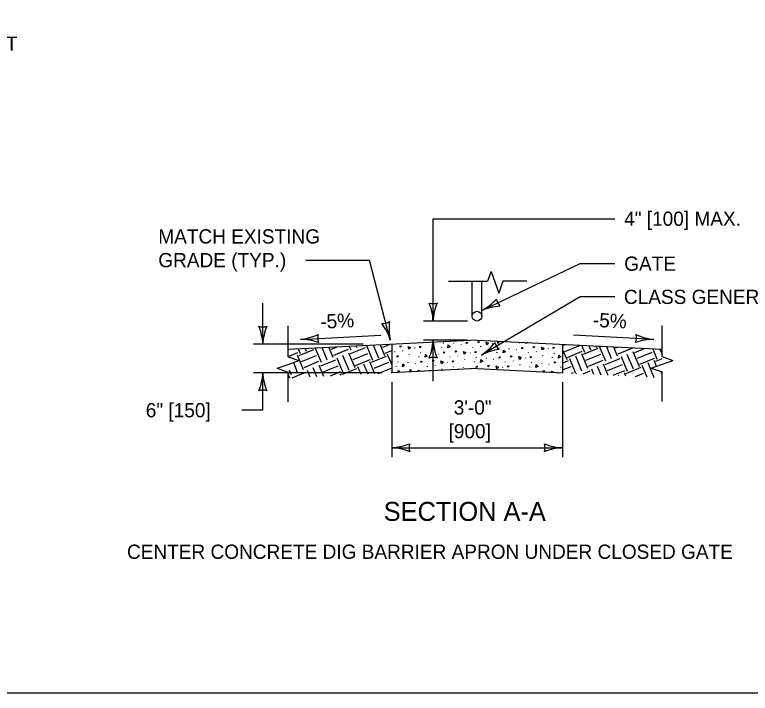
# Model space of a CAD drawing. Extents: x 49991.4 to 50021, y 49987.6 to 50011.4.
# Drawn here: x 50010.385 to 50013.487, y 49987.799 to 49990.66 of the extents above; entities that cross this region are included whole.
import ezdxf

# ---------------------------------------------------------------- set-up
doc = ezdxf.new("R2010")
doc.units = 0
for name, color, linetype in [('Level 1', 7, 'Continuous'), ('Level 2', 7, 'Continuous'), ('Level 3', 7, 'Continuous'), ('Level 6', 7, 'Continuous')]:
    doc.layers.add(name, color=color, linetype=linetype)

msp = doc.modelspace()

# ---------------------------------------------------------------- linework, layer by layer
at = {"layer": 'Level 1'}
for p, q in [((50012.3141, 49989.3891), (50012.3141, 49989.537)), ((50012.3552, 49989.3891), (50012.3552, 49989.537)), ((50012.3347, 49989.2886), (50011.5381, 49989.2488)), ((50012.3347, 49989.2886), (50013.1145, 49989.2496)), ((50011.6096, 49989.2524), (50011.6139, 49989.242)), ((50011.6096, 49989.2524), (50011.6139, 49989.242)), ((50011.6383, 49989.2538), (50011.6389, 49989.2524)), ((50011.6383, 49989.2538), (50011.6389, 49989.2524)), ((50011.6522, 49989.2545), (50011.6767, 49989.1952)), ((50011.6522, 49989.2545), (50011.6767, 49989.1952)), ((50011.6809, 49989.2559), (50011.7018, 49989.2056)), ((50011.6809, 49989.2559), (50011.7018, 49989.2056)), ((50011.7097, 49989.2574), (50011.7268, 49989.2159)), ((50011.7097, 49989.2574), (50011.7268, 49989.2159)), ((50011.7201, 49989.2498), (50011.7423, 49989.259)), ((50011.7201, 49989.2498), (50011.7423, 49989.259)), ((50011.7959, 49989.2617), (50011.802, 49989.2471)), ((50011.7959, 49989.2617), (50011.802, 49989.2471)), ((50011.8012, 49989.2312), (50011.8638, 49989.2572)), ((50011.8012, 49989.2312), (50011.8638, 49989.2572)), ((50011.8247, 49989.2631), (50011.827, 49989.2574)), ((50011.8247, 49989.2631), (50011.827, 49989.2574)), ((50011.8683, 49989.2653), (50011.8941, 49989.2032)), ((50011.8683, 49989.2653), (50011.8941, 49989.2032)), ((50011.8971, 49989.2667), (50011.9191, 49989.2135)), ((50011.8971, 49989.2667), (50011.9191, 49989.2135)), ((50011.9258, 49989.2682), (50011.9442, 49989.2239)), ((50011.9258, 49989.2682), (50011.9442, 49989.2239)), ((50011.9368, 49989.2581), (50011.966, 49989.2702)), ((50011.9368, 49989.2581), (50011.966, 49989.2702)), ((50011.9746, 49989.2706), (50011.9746, 49989.1505)), ((50012.0715, 49989.2564), (50012.0724, 49989.2547)), ((50012.1455, 49989.2658), (50012.1455, 49989.2679)), ((50012.1859, 49989.2565), (50012.186, 49989.2586)), ((50012.1916, 49989.2762), (50012.1929, 49989.2753)), ((50012.1926, 49989.2761), (50012.1938, 49989.2752)), ((50012.2362, 49989.272), (50012.2363, 49989.2741)), ((50012.2665, 49989.2695), (50012.2678, 49989.2686)), ((50012.3173, 49989.2556), (50012.3174, 49989.2577)), ((50012.3511, 49989.26), (50012.3512, 49989.2621)), ((50012.4008, 49989.2747), (50012.4017, 49989.273)), ((50012.425, 49989.2548), (50012.4263, 49989.2539)), ((50012.426, 49989.2546), (50012.4273, 49989.2538)), ((50012.4697, 49989.2505), (50012.4697, 49989.2526)), ((50012.5152, 49989.2747), (50012.5152, 49989.2769)), ((50012.6342, 49989.2532), (50012.6351, 49989.2515)), ((50012.6947, 49989.2706), (50012.6947, 49989.1505)), ((50012.6947, 49989.265), (50012.7068, 49989.27)), ((50012.7051, 49989.24), (50012.7677, 49989.2659)), ((50012.7753, 49989.2666), (50012.7876, 49989.2369)), ((50012.7833, 49989.2283), (50012.8459, 49989.2543)), ((50012.8053, 49989.2651), (50012.8127, 49989.2473)), ((50012.8353, 49989.2636), (50012.8377, 49989.2577)), ((50012.8497, 49989.2629), (50012.8755, 49989.2005)), ((50012.8797, 49989.2614), (50012.9006, 49989.2109)), ((50012.9096, 49989.2599), (50012.9256, 49989.2213)), ((50012.9189, 49989.2552), (50012.9281, 49989.259)), ((50012.9293, 49989.2301), (50012.9913, 49989.2558)), ((50012.9995, 49989.2554), (50013.0008, 49989.2524)), ((50013, 49989.2366), (50013.0405, 49989.2533)), ((50011.5381, 49989.2478), (50011.5408, 49989.2489)), ((50011.5381, 49989.2184), (50011.5793, 49989.2355)), ((50011.5756, 49989.2267), (50011.6016, 49989.164)), ((50011.5756, 49989.2267), (50011.6016, 49989.164)), ((50011.5808, 49989.2509), (50011.5888, 49989.2316)), ((50011.5808, 49989.2509), (50011.5888, 49989.2316)), ((50011.5845, 49989.223), (50011.6471, 49989.2489)), ((50011.5845, 49989.223), (50011.6471, 49989.2489)), ((50011.5949, 49989.198), (50011.6575, 49989.2239)), ((50011.5949, 49989.198), (50011.6575, 49989.2239)), ((50011.7305, 49989.2248), (50011.7931, 49989.2507)), ((50011.7305, 49989.2248), (50011.7931, 49989.2507)), ((50011.7679, 49989.2243), (50011.7939, 49989.1617)), ((50011.7679, 49989.2243), (50011.7939, 49989.1617)), ((50011.793, 49989.2347), (50011.8189, 49989.172)), ((50011.793, 49989.2347), (50011.8189, 49989.172)), ((50011.8116, 49989.2062), (50011.8742, 49989.2321)), ((50011.8116, 49989.2062), (50011.8742, 49989.2321)), ((50011.9472, 49989.233), (50011.9746, 49989.2444)), ((50011.9472, 49989.233), (50011.9746, 49989.2444)), ((50011.956, 49989.2294), (50011.9746, 49989.1845)), ((50011.956, 49989.2294), (50011.9746, 49989.1845)), ((50011.988, 49989.2374), (50011.9881, 49989.2395)), ((50012.0218, 49989.2418), (50012.0219, 49989.2439)), ((50012.0497, 49989.2261), (50012.0497, 49989.2282)), ((50012.0957, 49989.2365), (50012.097, 49989.2357)), ((50012.0967, 49989.2364), (50012.098, 49989.2355)), ((50012.1404, 49989.2323), (50012.1404, 49989.2344)), ((50012.1707, 49989.2298), (50012.172, 49989.2289)), ((50012.2553, 49989.2203), (50012.2553, 49989.2224)), ((50012.3049, 49989.235), (50012.3059, 49989.2333)), ((50012.3789, 49989.2443), (50012.379, 49989.2465)), ((50012.4193, 49989.235), (50012.4194, 49989.2372)), ((50012.5, 49989.2481), (50012.5013, 49989.2472)), ((50012.5507, 49989.2342), (50012.5508, 49989.2363)), ((50012.5845, 49989.2385), (50012.5846, 49989.2407)), ((50012.6124, 49989.2229), (50012.6124, 49989.225)), ((50012.6584, 49989.2333), (50012.6597, 49989.2324)), ((50012.6594, 49989.2332), (50012.6607, 49989.2323)), ((50012.6947, 49989.2488), (50012.7125, 49989.2058)), ((50012.7155, 49989.2149), (50012.7781, 49989.2409)), ((50012.7494, 49989.2216), (50012.7753, 49989.159)), ((50012.7744, 49989.232), (50012.8004, 49989.1694)), ((50012.7937, 49989.2033), (50012.8563, 49989.2292)), ((50012.9667, 49989.2296), (50012.9927, 49989.167)), ((50012.9918, 49989.24), (50013.0177, 49989.1774)), ((50013.0104, 49989.2115), (50013.073, 49989.2375)), ((50013.075, 49989.2516), (50013.0929, 49989.2085)), ((50013.105, 49989.2501), (50013.1145, 49989.2272)), ((50011.5601, 49989.1934), (50011.5765, 49989.1537)), ((50011.6053, 49989.1729), (50011.6679, 49989.1988)), ((50011.6053, 49989.1729), (50011.6679, 49989.1988)), ((50011.6759, 49989.1794), (50011.7386, 49989.2053)), ((50011.6759, 49989.1794), (50011.7386, 49989.2053)), ((50011.7429, 49989.2139), (50011.7688, 49989.1513)), ((50011.7429, 49989.2139), (50011.7688, 49989.1513)), ((50011.8219, 49989.1811), (50011.8846, 49989.2071)), ((50011.8219, 49989.1811), (50011.8846, 49989.2071)), ((50011.8809, 49989.1982), (50011.9022, 49989.1469)), ((50011.8809, 49989.1982), (50011.9022, 49989.1469)), ((50011.8898, 49989.1946), (50011.9524, 49989.2205)), ((50011.8898, 49989.1946), (50011.9524, 49989.2205)), ((50011.9001, 49989.1695), (50011.9628, 49989.1955)), ((50011.9001, 49989.1695), (50011.9628, 49989.1955)), ((50011.9999, 49989.1968), (50012.0012, 49989.196)), ((50012.0009, 49989.1967), (50012.0022, 49989.1958)), ((50012.0446, 49989.1926), (50012.0446, 49989.1947)), ((50012.0749, 49989.1901), (50012.0762, 49989.1892)), ((50012.0901, 49989.2168), (50012.0901, 49989.2189)), ((50012.2091, 49989.1953), (50012.21, 49989.1936)), ((50012.2215, 49989.2159), (50012.2215, 49989.218)), ((50012.2831, 49989.2046), (50012.2831, 49989.2068)), ((50012.3235, 49989.1953), (50012.3236, 49989.1975)), ((50012.3292, 49989.2151), (50012.3305, 49989.2142)), ((50012.3302, 49989.2149), (50012.3315, 49989.2141)), ((50012.3738, 49989.2108), (50012.3739, 49989.2129)), ((50012.4041, 49989.2084), (50012.4054, 49989.2075)), ((50012.4549, 49989.1945), (50012.455, 49989.1966)), ((50012.4887, 49989.1989), (50012.4888, 49989.201)), ((50012.5384, 49989.2135), (50012.5393, 49989.2118)), ((50012.5626, 49989.1936), (50012.5639, 49989.1927)), ((50012.5636, 49989.1935), (50012.5649, 49989.1926)), ((50012.6073, 49989.1893), (50012.6073, 49989.1915)), ((50012.6528, 49989.2136), (50012.6528, 49989.2157)), ((50012.6947, 49989.1916), (50012.7207, 49989.2024)), ((50012.7243, 49989.2113), (50012.7503, 49989.1486)), ((50012.8041, 49989.1782), (50012.8667, 49989.2042)), ((50012.8747, 49989.1847), (50012.9374, 49989.2106)), ((50012.9417, 49989.2192), (50012.9676, 49989.1566)), ((50013.0207, 49989.1865), (50013.0834, 49989.2124)), ((50013.0546, 49989.1932), (50013.0803, 49989.1312)), ((50013.0797, 49989.2036), (50013.0904, 49989.1778)), ((50013.0886, 49989.1999), (50013.1093, 49989.2085)), ((50013.1093, 49989.2085), (50013.1145, 49989.2106)), ((50011.5431, 49989.1635), (50011.5515, 49989.1433)), ((50011.5431, 49989.1635), (50011.5515, 49989.1433)), ((50011.6176, 49989.162), (50011.6296, 49989.1332)), ((50011.6176, 49989.162), (50011.6296, 49989.1332)), ((50011.6427, 49989.1724), (50011.6583, 49989.1347)), ((50011.6427, 49989.1724), (50011.6583, 49989.1347)), ((50011.6677, 49989.1828), (50011.6871, 49989.1361)), ((50011.6677, 49989.1828), (50011.6871, 49989.1361)), ((50011.6863, 49989.1543), (50011.7489, 49989.1803)), ((50011.6863, 49989.1543), (50011.7489, 49989.1803)), ((50011.7645, 49989.1427), (50011.8271, 49989.1686)), ((50011.7645, 49989.1427), (50011.8271, 49989.1686)), ((50011.8308, 49989.1775), (50011.8447, 49989.144)), ((50011.8308, 49989.1775), (50011.8447, 49989.144)), ((50011.8558, 49989.1879), (50011.8734, 49989.1454)), ((50011.8558, 49989.1879), (50011.8734, 49989.1454)), ((50011.9182, 49989.1477), (50011.9731, 49989.1704)), ((50011.9182, 49989.1477), (50011.9731, 49989.1704)), ((50012.3347, 49989.1685), (50011.9746, 49989.1505)), ((50011.9942, 49989.1771), (50011.9943, 49989.1792)), ((50012.1256, 49989.1762), (50012.1257, 49989.1783)), ((50012.1594, 49989.1806), (50012.1595, 49989.1827)), ((50012.1873, 49989.1649), (50012.1873, 49989.1671)), ((50012.2333, 49989.1754), (50012.2346, 49989.1745)), ((50012.2343, 49989.1752), (50012.2356, 49989.1744)), ((50012.278, 49989.1711), (50012.278, 49989.1732)), ((50012.3083, 49989.1687), (50012.3096, 49989.1678)), ((50012.3347, 49989.1685), (50012.6947, 49989.1505)), ((50012.4425, 49989.1738), (50012.4435, 49989.1721)), ((50012.5165, 49989.1832), (50012.5166, 49989.1853)), ((50012.5569, 49989.1739), (50012.557, 49989.176)), ((50012.6376, 49989.1869), (50012.6389, 49989.186)), ((50012.6883, 49989.173), (50012.6884, 49989.1751)), ((50012.6947, 49989.1623), (50012.7311, 49989.1773)), ((50012.8164, 49989.1674), (50012.8262, 49989.1439)), ((50012.8415, 49989.1777), (50012.8561, 49989.1424)), ((50012.8665, 49989.1881), (50012.8861, 49989.1409)), ((50012.8851, 49989.1597), (50012.9477, 49989.1856)), ((50012.9081, 49989.1398), (50012.9581, 49989.1605)), ((50012.9633, 49989.148), (50013.0259, 49989.174)), ((50013.0296, 49989.1828), (50013.0504, 49989.1327)), ((50011.5381, 49989.1451), (50011.5426, 49989.147)), ((50011.5381, 49989.1416), (50011.5433, 49989.1289)), ((50011.5392, 49989.1455), (50011.5426, 49989.147)), ((50011.5425, 49989.1309), (50011.5433, 49989.1289)), ((50011.5556, 49989.1295), (50011.6133, 49989.1534)), ((50011.5556, 49989.1295), (50011.6133, 49989.1534)), ((50011.7168, 49989.1376), (50011.7593, 49989.1552)), ((50011.7168, 49989.1376), (50011.7593, 49989.1552)), ((50011.7557, 49989.1463), (50011.7584, 49989.1397)), ((50011.7557, 49989.1463), (50011.7584, 49989.1397)), ((50011.973, 49989.1543), (50011.9746, 49989.1505)), ((50011.973, 49989.1543), (50011.9746, 49989.1505)), ((50012.676, 49989.1524), (50012.6765, 49989.1514)), ((50012.7325, 49989.1486), (50012.7414, 49989.1523)), ((50012.7816, 49989.1461), (50012.8121, 49989.1588)), ((50012.9294, 49989.1413), (50012.9305, 49989.1387)), ((50012.9544, 49989.1517), (50012.9605, 49989.1372)), ((50013.0029, 49989.1351), (50013.0363, 49989.1489)), ((50013.1093, 49989.1498), (50013.1145, 49989.1519))]:
    msp.add_line(p, q, dxfattribs=at)
msp.add_lwpolyline([(49999.3835, 49998.9992), (50016.7501, 49998.9992), (50016.7501, 49987.7988), (49999.3835, 49987.7988)], close=True, dxfattribs=at)
for points in [[(50012.0102, 49989.2586), (50012.0105, 49989.2646), (50012.0158, 49989.2633), (50012.0102, 49989.2586)], [(50012.047, 49989.2498), (50012.0439, 49989.2619), (50012.0541, 49989.2574), (50012.0472, 49989.2499)], [(50012.093, 49989.2562), (50012.0933, 49989.2622), (50012.0985, 49989.2609), (50012.093, 49989.2562)], [(50012.2115, 49989.2554), (50012.2126, 49989.2678), (50012.2207, 49989.2601), (50012.2117, 49989.2554)], [(50012.2897, 49989.273), (50012.29, 49989.279), (50012.2953, 49989.2777), (50012.2897, 49989.273)], [(50012.3395, 49989.2769), (50012.3398, 49989.2829), (50012.345, 49989.2815), (50012.3395, 49989.2769)], [(50012.3763, 49989.268), (50012.3731, 49989.2801), (50012.3834, 49989.2757), (50012.3765, 49989.2682)], [(50012.4222, 49989.2745), (50012.4226, 49989.2805), (50012.4278, 49989.2791), (50012.4222, 49989.2745)], [(50012.5231, 49989.2516), (50012.5235, 49989.2575), (50012.5287, 49989.2562), (50012.5231, 49989.2516)], [(50012.5407, 49989.2736), (50012.5412, 49989.2783)], [(50012.5491, 49989.2779), (50012.5409, 49989.2737)], [(50012.5729, 49989.2554), (50012.5732, 49989.2614), (50012.5785, 49989.2601), (50012.5729, 49989.2554)], [(50012.6097, 49989.2466), (50012.6066, 49989.2587), (50012.6168, 49989.2542), (50012.6099, 49989.2467)], [(50012.6557, 49989.253), (50012.656, 49989.259), (50012.6612, 49989.2577), (50012.6557, 49989.253)], [(50011.9971, 49989.2165), (50011.9975, 49989.2225), (50012.0027, 49989.2212), (50011.9971, 49989.2165)], [(50012.1156, 49989.2157), (50012.1168, 49989.2281), (50012.1249, 49989.2204), (50012.1158, 49989.2157)], [(50012.1939, 49989.2333), (50012.1942, 49989.2393), (50012.1994, 49989.238), (50012.1939, 49989.2333)], [(50012.2436, 49989.2372), (50012.244, 49989.2432), (50012.2492, 49989.2418), (50012.2436, 49989.2372)], [(50012.2805, 49989.2283), (50012.2773, 49989.2404), (50012.2875, 49989.236), (50012.2806, 49989.2285)], [(50012.3264, 49989.2348), (50012.3267, 49989.2408), (50012.332, 49989.2394), (50012.3264, 49989.2348)], [(50012.4449, 49989.2339), (50012.4461, 49989.2463), (50012.4542, 49989.2387), (50012.4451, 49989.234)], [(50012.4771, 49989.2157), (50012.4774, 49989.2217), (50012.4827, 49989.2204), (50012.4771, 49989.2157)], [(50012.6783, 49989.2125), (50012.6795, 49989.2249), (50012.6876, 49989.2172), (50012.6785, 49989.2125)], [(50012.098, 49989.1936), (50012.0984, 49989.1996), (50012.1036, 49989.1983), (50012.098, 49989.1936)], [(50012.1478, 49989.1975), (50012.1481, 49989.2035), (50012.1534, 49989.2021), (50012.1478, 49989.1975)], [(50012.1846, 49989.1886), (50012.1815, 49989.2007), (50012.1917, 49989.1963), (50012.1848, 49989.1888)], [(50012.2306, 49989.1951), (50012.2309, 49989.2011), (50012.2361, 49989.1997), (50012.2306, 49989.1951)], [(50012.3491, 49989.1942), (50012.3502, 49989.2067), (50012.3583, 49989.199), (50012.3493, 49989.1943)], [(50012.4273, 49989.2119), (50012.4276, 49989.2179), (50012.4329, 49989.2165), (50012.4273, 49989.2119)], [(50012.5139, 49989.2069), (50012.5108, 49989.219), (50012.521, 49989.2145), (50012.5141, 49989.207)], [(50012.5598, 49989.2133), (50012.5602, 49989.2193), (50012.5654, 49989.218), (50012.5598, 49989.2133)], [(50012.6607, 49989.1904), (50012.6611, 49989.1964), (50012.6663, 49989.1951), (50012.6607, 49989.1904)], [(50012.0022, 49989.1539), (50012.0025, 49989.1599), (50012.0078, 49989.1586), (50012.0022, 49989.1539)], [(50012.0198, 49989.176), (50012.021, 49989.1884), (50012.0291, 49989.1807), (50012.02, 49989.1761)], [(50012.052, 49989.1578), (50012.0523, 49989.1638), (50012.0575, 49989.1624), (50012.052, 49989.1578)], [(50012.0869, 49989.1563), (50012.0857, 49989.161), (50012.0956, 49989.1567)], [(50012.1349, 49989.1587), (50012.1351, 49989.1614), (50012.1403, 49989.16), (50012.139, 49989.159)], [(50012.2542, 49989.1649), (50012.2544, 49989.167), (50012.2564, 49989.165)], [(50012.3315, 49989.1722), (50012.3318, 49989.1782), (50012.337, 49989.1768), (50012.3315, 49989.1722)], [(50012.3812, 49989.176), (50012.3816, 49989.182), (50012.3868, 49989.1807), (50012.3812, 49989.176)], [(50012.4181, 49989.1672), (50012.4149, 49989.1793), (50012.4251, 49989.1748), (50012.4182, 49989.1673)], [(50012.464, 49989.1736), (50012.4643, 49989.1796), (50012.4696, 49989.1783), (50012.464, 49989.1736)], [(50012.5825, 49989.1728), (50012.5837, 49989.1852), (50012.5918, 49989.1775), (50012.5827, 49989.1728)], [(50012.6147, 49989.1546), (50012.615, 49989.1606), (50012.6203, 49989.1592), (50012.6147, 49989.1546)], [(50012.6497, 49989.1527), (50012.6484, 49989.1578), (50012.6586, 49989.1534), (50012.6576, 49989.1523)], [(50012.7518, 49989.1476), (50012.7518, 49989.1479), (50012.7532, 49989.1475)]]:
    msp.add_lwpolyline(points, dxfattribs=at)
msp.add_circle((50012.3347, 49989.3891), 0.0205, dxfattribs=at)
at = {"layer": 'Level 3'}
for p, q in [((50012.1494, 49989.3686), (50012.1494, 49989.8002)), ((50012.1494, 49989.8002), (50012.9149, 49989.8002)), ((50011.6122, 49989.6255), (50011.8811, 49989.6255)), ((50011.9687, 49989.2886), (50011.8811, 49989.6255)), ((50012.3552, 49989.4136), (50012.7695, 49989.6106)), ((50012.7695, 49989.6106), (50012.9149, 49989.6106)), ((50011.4314, 49989.2706), (50011.4314, 49989.444)), ((50012.2947, 49989.3686), (50012.1094, 49989.3686)), ((50011.5896, 49989.2914), (50011.9286, 49989.3084)), ((50012.2947, 49989.2886), (50012.1094, 49989.2886)), ((50012.1494, 49989.1152), (50012.1494, 49989.2886)), ((50013.0797, 49989.2914), (50012.7407, 49989.3084)), ((50011.8546, 49989.2706), (50011.3914, 49989.2706)), ((50011.9346, 49989.1505), (50011.3914, 49989.1505)), ((50011.4314, 49988.9926), (50011.4314, 49989.1505)), ((50011.9746, 49989.1105), (50011.9746, 49988.7943)), ((50012.6947, 49989.1105), (50012.6947, 49988.7943)), ((50011.4314, 49988.9926), (50011.3429, 49988.9926)), ((50011.9746, 49988.8343), (50012.6947, 49988.8343))]:
    msp.add_line(p, q, dxfattribs=at)
msp.add_lwpolyline([(50012.9149, 49989.4706), (50012.7695, 49989.4706), (50012.3533, 49989.2253)], dxfattribs=at)
for centre, radius, start, end in [((50012.1494, 49989.4968), 0.0548, 252.1388, 287.8612), ((50011.9166, 49989.3571), 0.233, 2.8273, 22.0772), ((50012.3715, 49989.3595), 0.2223, 157.456, 177.6395), ((50012.2449, 49989.6188), 0.233, 298.264, 317.5139), ((50012.471, 49989.4686), 0.0548, 187.5755, 223.2979), ((50012.4423, 49989.209), 0.2223, 92.8927, 113.0762), ((50011.4314, 49989.3988), 0.0548, 252.1388, 287.8612), ((50011.1987, 49989.2591), 0.233, 2.8273, 22.0772), ((50011.6535, 49989.2615), 0.2223, 157.456, 177.6395), ((50011.9365, 49989.4127), 0.0548, 266.7223, 302.4447), ((50011.7464, 49989.2189), 0.233, 17.4108, 36.6606), ((50012.186, 49989.3357), 0.2223, 172.0395, 192.223), ((50011.5665, 49989.5233), 0.233, 275.6897, 294.9396), ((50011.5915, 49989.0691), 0.2223, 70.3184, 90.5019), ((50011.7176, 49989.2978), 0.0548, 165.0012, 200.7236), ((50011.9272, 49989.2978), 0.2223, 337.456, 357.6395), ((50012.3821, 49989.3001), 0.233, 182.8273, 202.0772), ((50012.9517, 49989.2978), 0.0548, 339.2764, 14.9988), ((50013.0796, 49989.0584), 0.233, 89.9649, 109.2148), ((50013.1, 49989.5128), 0.2223, 244.5936, 264.7771), ((50012.2252, 49989.42), 0.233, 303.3355, 322.5853), ((50012.4637, 49989.2904), 0.0548, 192.647, 228.3693), ((50012.4581, 49989.0293), 0.2223, 97.9642, 118.1477), ((50012.1494, 49989.1604), 0.0548, 72.1388, 107.8612), ((50011.2092, 49989.1596), 0.2223, 337.456, 357.6395), ((50011.6641, 49989.162), 0.233, 182.8273, 202.0772), ((50011.4314, 49989.0223), 0.0548, 72.1388, 107.8612), ((50011.9632, 49989.067), 0.233, 272.8273, 292.0772), ((50012.1029, 49988.8343), 0.0548, 162.1388, 197.8612), ((50012.7038, 49989.0564), 0.2223, 247.456, 267.6395), ((50012.5665, 49988.8343), 0.0548, 342.1388, 17.8612), ((50011.9655, 49988.6121), 0.2223, 67.456, 87.6395), ((50012.7062, 49988.6015), 0.233, 92.8273, 112.0772)]:
    msp.add_arc(centre, radius, start, end, dxfattribs=at)
at = {"layer": 'Level 6'}
for p, q in [((50012.3934, 49989.5774), (50012.3791, 49989.537)), ((50012.3934, 49989.5774), (50012.4258, 49989.486)), ((50012.2141, 49989.537), (50012.3791, 49989.537)), ((50012.4439, 49989.537), (50012.4258, 49989.486)), ((50012.5439, 49989.537), (50012.4439, 49989.537)), ((50011.5381, 49989.218), (50011.5381, 49989.3488)), ((50013.1145, 49989.2188), (50013.1145, 49989.3496)), ((50011.5381, 49989.218), (50011.5838, 49989.2018)), ((50011.5381, 49989.1856), (50011.5838, 49989.2018)), ((50013.0688, 49989.1702), (50013.1602, 49989.2026)), ((50013.1145, 49989.2188), (50013.1602, 49989.2026)), ((50011.4924, 49989.1694), (50011.5381, 49989.1856)), ((50011.4924, 49989.1694), (50011.5381, 49989.1532)), ((50013.0688, 49989.1702), (50013.1145, 49989.154)), ((50011.5381, 49989.0284), (50011.5381, 49989.1532)), ((50013.1145, 49989.0294), (50013.1145, 49989.154))]:
    msp.add_line(p, q, dxfattribs=at)

# ---------------------------------------------------------------- texts
at = {"layer": 'Level 2'}
for s, height, p in [('7" [180] DIA. WOOD POST', 0.060003, (50009.4233, 49990.5083)), ('4" [100] MAX.', 0.06, (50012.9549, 49989.7702)), ('MATCH EXISTING', 0.06, (50010.9906, 49989.6955)), ('GRADE (TYP.)', 0.06, (50010.9906, 49989.5955)), ('GATE', 0.06, (50012.9549, 49989.5806)), ('CLASS GENERAL CONCRETE', 0.060003, (50012.9539, 49989.4406)), ('3\'-0"', 0.06, (50012.2362, 49988.9743)), ('[900]', 0.06, (50012.2144, 49988.8743)), ('SECTION A-A', 0.08, (50011.941, 49988.5258)), ('CENTER CONCRETE DIG BARRIER APRON UNDER CLOSED GATE', 0.060003, (50010.8586, 49988.3658))]:
    msp.add_text(s, height=height, dxfattribs=at).set_placement(p)
for s, rotation, p in [('-5%', 2.8624, (50011.6751, 49989.3357)), ('-5%', 357.1376, (50012.8217, 49989.3443)), ('6" [150]', 360, (50010.9379, 49988.9626))]:
    msp.add_text(s, height=0.06, rotation=rotation, dxfattribs=at).set_placement(p)

doc.saveas('drawing.dxf')
